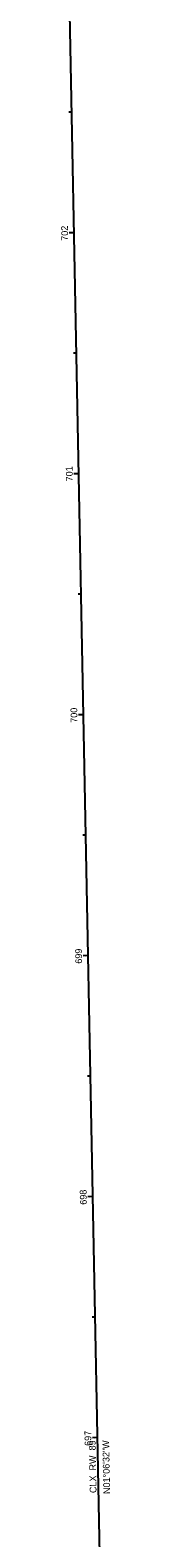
# Model space of a CAD drawing. Extents: x 2045805 to 2050091, y 455249 to 458900.
# Drawn here: x 2047631 to 2047665, y 456093 to 456718 of the extents above; entities that cross this region are included whole.
import ezdxf

# ---------------------------------------------------------------- set-up
doc = ezdxf.new("R2010")
doc.units = 0
for name, color, linetype in [('GE_P_Alignment_100_Cardinal_Points', 7, 'Continuous'), ('GE_P_Alignment_100_Curve_Data', 7, 'Continuous'), ('GE_P_Alignment_100_Stations', 7, 'Continuous'), ('GE_P_Driveway_CL', 7, 'Continuous'), ('PF_X_Ground_Line', 7, 'Continuous'), ('PV_P_EOP', 7, 'Continuous'), ('PV_X_EOP', 7, 'Continuous'), ('RW_X_CL_100_Stations', 7, 'Continuous'), ('SC_Scratch1', 7, 'Continuous'), ('SC_Scratch3', 7, 'Continuous')]:
    doc.layers.add(name, color=color, linetype=linetype)

msp = doc.modelspace()

# ---------------------------------------------------------------- linework, layer by layer
at = {"layer": 'GE_P_Alignment_100_Cardinal_Points'}
for p, q in [((2047637.19, 456684.34), (2047635.99, 456684.32)), ((2047638.16, 456634.35), (2047636.16, 456634.31)), ((2047639.12, 456584.36), (2047637.92, 456584.34)), ((2047640.09, 456534.37), (2047638.09, 456534.33)), ((2047641.06, 456484.38), (2047639.86, 456484.35)), ((2047642.03, 456434.39), (2047640.03, 456434.35)), ((2047642.99, 456384.4), (2047641.79, 456384.37)), ((2047643.96, 456334.41), (2047641.96, 456334.37)), ((2047644.93, 456284.42), (2047643.73, 456284.39)), ((2047645.9, 456234.42), (2047643.9, 456234.39)), ((2047646.87, 456184.43), (2047645.67, 456184.41)), ((2047647.83, 456134.44), (2047645.83, 456134.4))]:
    msp.add_line(p, q, dxfattribs=at)
at = {"layer": 'GE_P_Alignment_100_Stations'}
for p, q in [((2047638.16, 456634.35), (2047636.96, 456634.33)), ((2047640.09, 456534.37), (2047638.89, 456534.35)), ((2047642.03, 456434.39), (2047640.03, 456434.35)), ((2047643.96, 456334.41), (2047642.76, 456334.38)), ((2047645.9, 456234.42), (2047644.7, 456234.4)), ((2047647.83, 456134.44), (2047646.63, 456134.42))]:
    msp.add_line(p, q, dxfattribs=at)
at = {"layer": 'PV_P_EOP'}
msp.add_line((2047664.96, 455249.53), (2047631.15, 456996.2), dxfattribs=at)
at = {"layer": 'PV_X_EOP'}
msp.add_line((2047642.03, 456434.39), (2047640.03, 456434.35), dxfattribs=at)

# ---------------------------------------------------------------- texts
at = {"layer": 'GE_P_Alignment_100_Cardinal_Points'}
for s, p in [('702', (2047635.67, 456631.03)), ('701', (2047637.61, 456531.21)), ('700', (2047639.54, 456431.06)), ('699', (2047641.48, 456331.1)), ('698', (2047643.41, 456231.1)), ('697', (2047645.35, 456131.06))]:
    msp.add_text(s, height=2.8, rotation=91.10893, dxfattribs=at).set_placement(p)
at = {"layer": 'GE_P_Alignment_100_Curve_Data'}
msp.add_text('N01°06\'32"W', height=2.8, rotation=91.10893, dxfattribs=at).set_placement((2047653.09, 456111.09))
at = {"layer": 'GE_P_Alignment_100_Stations'}
msp.add_text('700', height=2.8, rotation=91.10893, dxfattribs=at).set_placement((2047639.54, 456431.06))
at = {"layer": 'GE_P_Driveway_CL'}
msp.add_text('CLX_RW_89', height=2.8, rotation=91.10893, dxfattribs=at).set_placement((2047647.45, 456111.48))
at = {"layer": 'PF_X_Ground_Line'}
msp.add_text('N01°06\'32"W', height=2.8, rotation=91.10893, dxfattribs=at).set_placement((2047653.09, 456111.09))
at = {"layer": 'PV_X_EOP'}
msp.add_text('700', height=2.8, rotation=91.10893, dxfattribs=at).set_placement((2047639.54, 456431.06))
at = {"layer": 'RW_X_CL_100_Stations'}
msp.add_text('CLX_RW_89', height=2.8, rotation=91.10893, dxfattribs=at).set_placement((2047647.45, 456111.48))
at = {"layer": 'SC_Scratch1'}
msp.add_text('N01°06\'32"W', height=2.8, rotation=91.10893, dxfattribs=at).set_placement((2047653.09, 456111.09))
at = {"layer": 'SC_Scratch3'}
msp.add_text('CLX_RW_89', height=2.8, rotation=91.10893, dxfattribs=at).set_placement((2047647.45, 456111.48))

doc.saveas('drawing.dxf')
